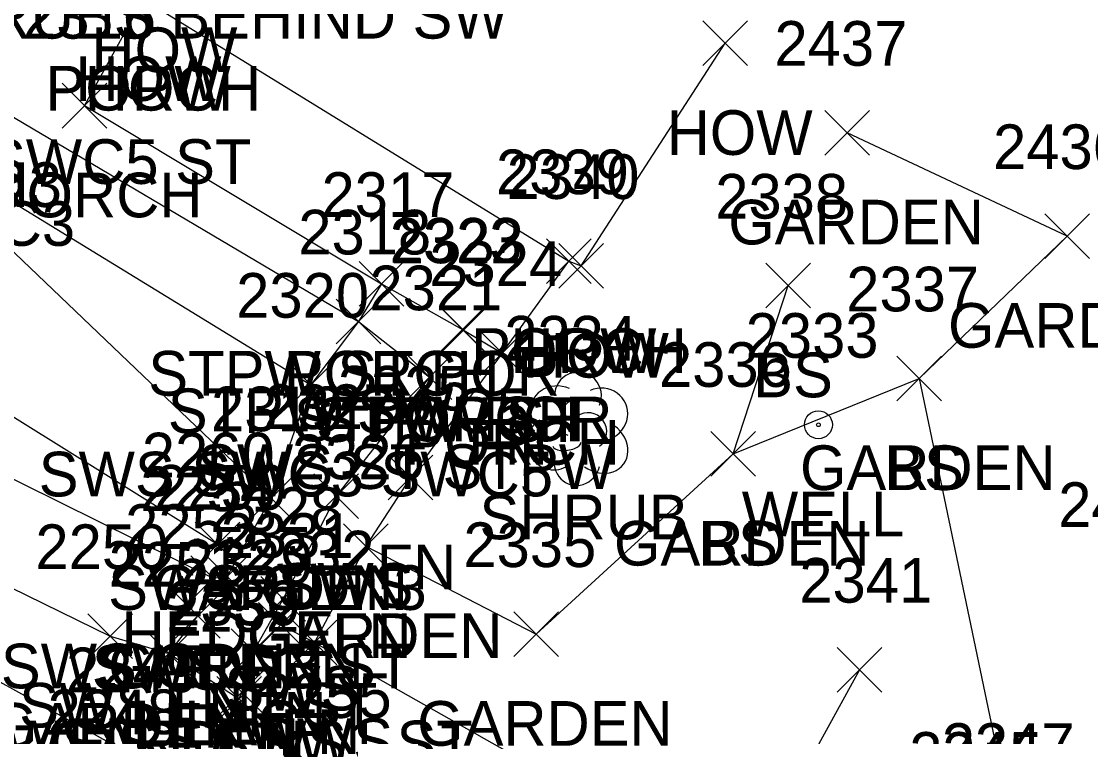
# Model space of a CAD drawing. Extents: x 1499292 to 1501024, y 534584 to 538043.
# Drawn here: x 1499393.02 to 1499440.89, y 537976.07 to 538008.09 of the extents above; entities that cross this region are included whole.
import ezdxf

# ---------------------------------------------------------------- set-up
doc = ezdxf.new("R2010")
doc.units = 0
for name, color, linetype in [('L_A', 7, 'Continuous'), ('L_C', 7, 'Continuous'), ('L_I', 7, 'Continuous'), ('L_TIC', 7, 'Continuous'), ('LAHR', 7, 'Continuous'), ('LAPB', 7, 'Continuous'), ('LBC', 7, 'Continuous'), ('LBF', 7, 'Continuous'), ('LDEFAULT', 7, 'Continuous'), ('LELB', 7, 'Continuous'), ('LFNC', 7, 'Continuous'), ('LSH', 7, 'Continuous'), ('R_A', 7, 'Continuous'), ('R_C', 7, 'Continuous'), ('R_I', 7, 'Continuous'), ('R_TIC', 7, 'Continuous'), ('RSW', 7, 'Continuous'), ('U_A', 7, 'Continuous'), ('U_I', 7, 'Continuous'), ('UWW', 7, 'Continuous')]:
    doc.layers.add(name, color=color, linetype=linetype)

msp = doc.modelspace()

# ---------------------------------------------------------------- linework, layer by layer
at = {"layer": 'L_TIC'}
for points in [[(1499423.526, 538006.115), (1499425.526, 538008.115)], [(1499425.526, 538006.115), (1499423.526, 538008.115)], [(1499394.843, 538003.32), (1499396.843, 538005.32)], [(1499396.843, 538003.32), (1499394.843, 538005.32)], [(1499428.997, 538002.107), (1499430.997, 538004.107)], [(1499430.997, 538002.107), (1499428.997, 538004.107)], [(1499438.84, 537997.481), (1499440.84, 537999.481)], [(1499440.84, 537997.481), (1499438.84, 537999.481)], [(1499416.535, 537996.356), (1499418.535, 537998.356)], [(1499418.535, 537996.356), (1499416.535, 537998.356)], [(1499416.535, 537996.356), (1499418.535, 537998.356)], [(1499418.535, 537996.356), (1499416.535, 537998.356)], [(1499417.089, 537996.143), (1499419.089, 537998.143)], [(1499419.089, 537996.143), (1499417.089, 537998.143)], [(1499408.149, 537995.339), (1499410.149, 537997.339)], [(1499410.149, 537995.339), (1499408.149, 537997.339)], [(1499408.149, 537995.339), (1499410.149, 537997.339)], [(1499410.149, 537995.339), (1499408.149, 537997.339)], [(1499426.345, 537995.262), (1499428.345, 537997.262)], [(1499428.345, 537995.262), (1499426.345, 537997.262)], [(1499407.109, 537993.658), (1499409.109, 537995.658)], [(1499409.109, 537993.658), (1499407.109, 537995.658)], [(1499411.769, 537993.292), (1499413.769, 537995.292)], [(1499413.769, 537993.292), (1499411.769, 537995.292)], [(1499411.769, 537993.292), (1499413.769, 537995.292)], [(1499413.769, 537993.292), (1499411.769, 537995.292)], [(1499411.818, 537993.265), (1499413.818, 537995.265)], [(1499413.818, 537993.265), (1499411.818, 537995.265)], [(1499413.542, 537992.243), (1499415.542, 537994.243)], [(1499415.542, 537992.243), (1499413.542, 537994.243)], [(1499413.542, 537992.243), (1499415.542, 537994.243)], [(1499415.542, 537992.243), (1499413.542, 537994.243)], [(1499410.293, 537991.159), (1499412.293, 537993.159)], [(1499412.293, 537991.159), (1499410.293, 537993.159)], [(1499432.212, 537991.11), (1499434.212, 537993.11)], [(1499434.212, 537991.11), (1499432.212, 537993.11)], [(1499432.212, 537991.11), (1499434.212, 537993.11)], [(1499434.212, 537991.11), (1499432.212, 537993.11)], [(1499423.882, 537987.729), (1499425.882, 537989.729)], [(1499425.882, 537987.729), (1499423.882, 537989.729)], [(1499423.882, 537987.729), (1499425.882, 537989.729)], [(1499425.882, 537987.729), (1499423.882, 537989.729)], [(1499409.444, 537986.67), (1499411.444, 537988.67)], [(1499411.444, 537986.67), (1499409.444, 537988.67)], [(1499403.208, 537985.742), (1499405.208, 537987.742)], [(1499405.208, 537985.742), (1499403.208, 537987.742)], [(1499400.802, 537983.677), (1499402.802, 537985.677)], [(1499402.802, 537983.677), (1499400.802, 537985.677)], [(1499407.442, 537983.592), (1499409.442, 537985.592)], [(1499409.442, 537983.592), (1499407.442, 537985.592)], [(1499407.442, 537983.592), (1499409.442, 537985.592)], [(1499409.442, 537983.592), (1499407.442, 537985.592)], [(1499400.597, 537982.165), (1499402.597, 537984.165)], [(1499402.597, 537982.165), (1499400.597, 537984.165)], [(1499401.231, 537982.233), (1499403.231, 537984.233)], [(1499403.231, 537982.233), (1499401.231, 537984.233)], [(1499399.924, 537980.478), (1499401.924, 537982.478)], [(1499401.924, 537980.478), (1499399.924, 537982.478)], [(1499403.63, 537980.073), (1499405.63, 537982.073)], [(1499405.63, 537980.073), (1499403.63, 537982.073)], [(1499395.992, 537979.573), (1499397.992, 537981.573)], [(1499397.992, 537979.573), (1499395.992, 537981.573)], [(1499405.14, 537979.287), (1499407.14, 537981.287)], [(1499407.14, 537979.287), (1499405.14, 537981.287)], [(1499405.14, 537979.287), (1499407.14, 537981.287)], [(1499407.14, 537979.287), (1499405.14, 537981.287)], [(1499415.069, 537979.662), (1499417.069, 537981.662)], [(1499417.069, 537979.662), (1499415.069, 537981.662)], [(1499398.613, 537978.785), (1499400.613, 537980.785)], [(1499400.613, 537978.785), (1499398.613, 537980.785)], [(1499402.414, 537978.895), (1499404.414, 537980.895)], [(1499404.414, 537978.895), (1499402.414, 537980.895)], [(1499429.543, 537978.068), (1499431.543, 537980.068)], [(1499431.543, 537978.068), (1499429.543, 537980.068)], [(1499401.888, 537977.055), (1499403.888, 537979.055)], [(1499403.888, 537977.055), (1499401.888, 537979.055)], [(1499401.766, 537976.763), (1499403.766, 537978.763)], [(1499403.766, 537976.763), (1499401.766, 537978.763)]]:
    msp.add_lwpolyline(points, dxfattribs=at)
at = {"layer": 'LAHR'}
msp.add_lwpolyline([(1499401.802, 537984.677), (1499380.829, 537997.746), (1499371.736, 538001.851), (1499353.026, 538009.497), (1499334.448, 538017.089)], dxfattribs=at)
at = {"layer": 'LAPB'}
for points in [[(1499344.944, 538025.151), (1499343.901, 538021.262), (1499346.481, 538015.016), (1499362.247, 538007.977), (1499372.995, 538003.698), (1499385.306, 538004.783), (1499404.208, 537986.742)], [(1499325.056, 538023.466), (1499322.984, 538022.224), (1499326.041, 538014.699), (1499358.955, 537999.2), (1499396.992, 537980.573), (1499399.613, 537979.785)], [(1499408.442, 537984.592), (1499416.069, 537980.662), (1499424.882, 537988.729), (1499433.212, 537992.11), (1499439.84, 537998.481), (1499429.997, 538003.107)], [(1499402.766, 537977.763), (1499406.906, 537973.904), (1499417.988, 537967.537)]]:
    msp.add_lwpolyline(points, dxfattribs=at)
at = {"layer": 'LBC'}
msp.add_lwpolyline([(1499398.301, 538013.468), (1499398.768, 538010.822), (1499398.055, 538009.531), (1499398.472, 538009.099), (1499417.535, 537997.356), (1499418.089, 537997.143), (1499424.526, 538007.115)], dxfattribs=at)
at = {"layer": 'LBF'}
for points in [[(1499398.472, 538009.099), (1499395.843, 538004.32), (1499409.149, 537996.339), (1499412.769, 537994.292), (1499414.542, 537993.243), (1499417.535, 537997.356)], [(1499409.149, 537996.339), (1499408.109, 537994.658), (1499411.293, 537992.159)], [(1499412.818, 537994.265), (1499412.769, 537994.292)]]:
    msp.add_lwpolyline(points, dxfattribs=at)
at = {"layer": 'LDEFAULT'}
msp.add_lwpolyline([(1499430.543, 537979.068), (1499425.72, 537970.292)], dxfattribs=at)
at = {"layer": 'LELB'}
for points in [[(1499318.383, 538015.127), (1499358.346, 537997.221), (1499398.285, 537975.056), (1499417.456, 537965.302)], [(1499424.882, 537988.729), (1499427.345, 537996.262)], [(1499433.212, 537992.11), (1499437.487, 537971.67)]]:
    msp.add_lwpolyline(points, dxfattribs=at)
at = {"layer": 'LFNC'}
for points in [[(1499325.056, 538023.466), (1499329.165, 538016.232), (1499360.338, 538003.615), (1499401.597, 537983.165)], [(1499414.542, 537993.243), (1499410.444, 537987.67), (1499408.442, 537984.592), (1499406.14, 537980.287)], [(1499403.414, 537979.895), (1499404.63, 537981.073), (1499406.14, 537980.287), (1499425.77, 537969.179)]]:
    msp.add_lwpolyline(points, dxfattribs=at)
at = {"layer": 'LSH'}
msp.add_line((1499417.899, 537989.907), (1499417.899, 537989.907), dxfattribs=at)
msp.add_line((1499417.899, 537989.907), (1499417.899, 537989.907), dxfattribs=at)
msp.add_arc((1499417.945, 537991.341), 1.047, 335.5272, 180.9563, dxfattribs=at)
for centre, major_axis, ratio, start_param, end_param in [((1499417.107, 537990.574), (1.21, -0.512), 0.895232, 1.570796, 4.712389), ((1499418.94, 537990.491), (-1.141, -0.483), 0.949671, 1.570796, 4.712389), ((1499417.69, 537990.365), (-0.208, -0.792), 0.645439, 3.141593, 6.283185), ((1499418.399, 537989.74), (-0.5, 0.667), 0.989748, 3.141593, 6.283185), ((1499416.815, 537989.199), (0.584, -1.042), 0.959034, 3.141593, 6.283185), ((1499418.899, 537989.074), (-1.09, 0.792), 0.841452, 1.570796, 4.712389), ((1499417.44, 537989.157), (-0.625, -0.083), 0.423636, 0, 3.141593), ((1499417.899, 537988.407), (0.265, 1.061), 0.942809, 1.570796, 4.712389)]:
    msp.add_ellipse(centre, major_axis=major_axis, ratio=ratio, start_param=start_param, end_param=end_param, dxfattribs=at)
at = {"layer": 'R_TIC'}
for points in [[(1499407.109, 537993.658), (1499409.109, 537995.658)], [(1499409.109, 537993.658), (1499407.109, 537995.658)], [(1499404.981, 537990.826), (1499406.981, 537992.826)], [(1499406.981, 537990.826), (1499404.981, 537992.826)], [(1499404.981, 537990.826), (1499406.981, 537992.826)], [(1499406.981, 537990.826), (1499404.981, 537992.826)], [(1499404.981, 537990.826), (1499406.981, 537992.826)], [(1499406.981, 537990.826), (1499404.981, 537992.826)], [(1499410.293, 537991.159), (1499412.293, 537993.159)], [(1499412.293, 537991.159), (1499410.293, 537993.159)], [(1499403.208, 537985.742), (1499405.208, 537987.742)], [(1499405.208, 537985.742), (1499403.208, 537987.742)], [(1499406.116, 537985.84), (1499408.116, 537987.84)], [(1499408.116, 537985.84), (1499406.116, 537987.84)], [(1499400.597, 537982.165), (1499402.597, 537984.165)], [(1499402.597, 537982.165), (1499400.597, 537984.165)], [(1499401.231, 537982.233), (1499403.231, 537984.233)], [(1499403.231, 537982.233), (1499401.231, 537984.233)], [(1499403.737, 537981.239), (1499405.737, 537983.239)], [(1499405.737, 537981.239), (1499403.737, 537983.239)], [(1499399.924, 537980.478), (1499401.924, 537982.478)], [(1499401.924, 537980.478), (1499399.924, 537982.478)], [(1499398.613, 537978.785), (1499400.613, 537980.785)], [(1499400.613, 537978.785), (1499398.613, 537980.785)], [(1499398.613, 537978.785), (1499400.613, 537980.785)], [(1499400.613, 537978.785), (1499398.613, 537980.785)], [(1499402.414, 537978.895), (1499404.414, 537980.895)], [(1499404.414, 537978.895), (1499402.414, 537980.895)], [(1499401.888, 537977.055), (1499403.888, 537979.055)], [(1499403.888, 537977.055), (1499401.888, 537979.055)], [(1499401.888, 537977.055), (1499403.888, 537979.055)], [(1499403.888, 537977.055), (1499401.888, 537979.055)], [(1499401.766, 537976.763), (1499403.766, 537978.763)], [(1499403.766, 537976.763), (1499401.766, 537978.763)]]:
    msp.add_lwpolyline(points, dxfattribs=at)
at = {"layer": 'RSW'}
for points in [[(1499389.242, 538005.816), (1499387.656, 538003.043), (1499405.981, 537991.826)], [(1499389.242, 538005.816), (1499408.109, 537994.658), (1499405.981, 537991.826)], [(1499399.613, 537979.785), (1499400.924, 537981.478), (1499401.597, 537983.165), (1499402.231, 537983.233), (1499404.208, 537986.742), (1499405.981, 537991.826)], [(1499411.293, 537992.159), (1499407.116, 537986.84), (1499404.737, 537982.239), (1499403.414, 537979.895), (1499402.888, 537978.055)], [(1499399.613, 537979.785), (1499402.766, 537977.763), (1499402.888, 537978.055)]]:
    msp.add_lwpolyline(points, dxfattribs=at)
at = {"layer": 'UWW'}
for radius in [0.625, 0.0833]:
    msp.add_circle((1499428.707, 537990.032), radius, dxfattribs=at)

# ---------------------------------------------------------------- texts
at = {"layer": 'L_A'}
for s, p in [('HOW', (1499396.154, 538005.822)), ('HOW', (1499395.441, 538004.531)), ('PORCH', (1499394.094, 538004.099)), ('HOW', (1499395.858, 538004.099)), ('HOW', (1499421.912, 538002.115)), ('PORCH', (1499391.465, 537999.32)), ('GARDEN', (1499424.667, 537998.107)), ('GARDEN', (1499434.509, 537993.481)), ('PORCH', (1499413.157, 537992.356)), ('HOW', (1499414.921, 537992.356)), ('HOW', (1499415.475, 537992.143)), ('STPW ST POR', (1499398.7, 537991.339)), ('PORCH', (1499404.771, 537991.339)), ('BS', (1499425.785, 537991.262)), ('STPW SWC5', (1499399.574, 537989.658)), ('STPW POR', (1499405.218, 537989.292)), ('PORCH', (1499408.391, 537989.292)), ('STPW ST', (1499406.211, 537989.265)), ('PORCH', (1499410.164, 537988.243)), ('FN', (1499413.023, 537988.243)), ('SWS ST STPW', (1499400.883, 537987.159)), ('GARDEN', (1499427.881, 537987.11)), ('BS', (1499431.653, 537987.11)), ('SHRUB', (1499413.528, 537984.907)), ('GARDEN', (1499419.552, 537983.729)), ('BS', (1499423.323, 537983.729)), ('FN', (1499408.924, 537982.67)), ('GARDEN', (1499398.878, 537981.742)), ('HEDGE', (1499397.503, 537979.677)), ('GARDEN', (1499403.112, 537979.592)), ('FN', (1499406.923, 537979.592)), ('GARDEN', (1499396.901, 537978.233)), ('FN', (1499400.077, 537978.165)), ('FN', (1499399.404, 537976.478)), ('FN', (1499403.111, 537976.073)), ('GARDEN', (1499391.661, 537975.573)), ('GARDEN', (1499410.738, 537975.662)), ('FN', (1499404.621, 537975.287)), ('FN', (1499404.621, 537975.287)), ('GARDEN', (1499394.283, 537974.785)), ('FN', (1499401.894, 537974.895))]:
    msp.add_text(s, height=2, dxfattribs=at).set_placement(p)
at = {"layer": 'L_C'}
msp.add_text('LILAC', height=2, dxfattribs=at).set_placement((1499398.078, 537975.677))
at = {"layer": 'L_I'}
for s, p in [('2316', (1499393.095, 538007.32)), ('2437', (1499426.737, 538006.107)), ('2436', (1499436.525, 538001.481)), ('2339', (1499414.267, 538000.356)), ('2339', (1499414.267, 538000.356)), ('2340', (1499414.743, 538000.143)), ('2317', (1499406.456, 537999.339)), ('2317', (1499406.456, 537999.339)), ('2338', (1499424.085, 537999.262)), ('2318', (1499405.416, 537997.658)), ('2323', (1499409.509, 537997.292)), ('2323', (1499409.509, 537997.292)), ('2322', (1499409.558, 537997.265)), ('2324', (1499411.282, 537996.243)), ('2324', (1499411.282, 537996.243)), ('2321', (1499408.6, 537995.159)), ('2337', (1499429.952, 537995.11)), ('2337', (1499429.952, 537995.11)), ('2334', (1499414.639, 537992.907)), ('2336', (1499421.567, 537991.729)), ('2336', (1499421.567, 537991.729)), ('2325', (1499407.184, 537990.67)), ('2319', (1499401.508, 537989.742)), ('2260', (1499398.408, 537987.677)), ('2326', (1499405.128, 537987.592)), ('2326', (1499405.128, 537987.592)), ('2254', (1499398.337, 537986.165)), ('2259', (1499398.964, 537986.233)), ('2434', (1499439.443, 537985.457)), ('2253', (1499397.664, 537984.478)), ('2331', (1499401.938, 537984.073)), ('2250', (1499393.645, 537983.573)), ('2335', (1499412.809, 537983.662)), ('2332', (1499402.88, 537983.287)), ('2332', (1499402.88, 537983.287)), ('2251', (1499396.921, 537982.785)), ('2329', (1499400.146, 537982.895)), ('2341', (1499427.85, 537982.068)), ('2252', (1499399.506, 537980.763)), ('2330', (1499399.542, 537981.055)), ('2249', (1499395.017, 537978.056)), ('2255', (1499403.646, 537976.904)), ('2248', (1499394.188, 537976.179)), ('2347', (1499434.227, 537974.67)), ('2345', (1499432.773, 537974.274))]:
    msp.add_text(s, height=2, dxfattribs=at).set_placement(p)
at = {"layer": 'R_A'}
for s, p in [('SWS5 SWC3 ST SWC5 ST', (1499370.478, 538000.816)), ('SWS5 SWC3 ST SWC5 ST', (1499370.478, 538000.816)), ('SWS5 SWC3 ST SWC5 ST', (1499370.478, 538000.816)), ('SWS3 TS3 GDN3', (1499373.432, 537999.783)), ('SWS3 SWC3', (1499379.373, 537998.043)), ('SWS3 SWC3', (1499379.373, 537998.043)), ('STPW SWC5', (1499399.574, 537989.658)), ('SWS ST STPW', (1499400.883, 537987.159)), ('SWS SWC3 SWC5', (1499393.792, 537986.826)), ('SWS SWC3 SWC5', (1499393.792, 537986.826)), ('SWS SWC3 SWC5', (1499393.792, 537986.826)), ('SWS GDN3', (1499396.901, 537981.742)), ('SWS', (1499404.486, 537981.84)), ('SWS GDN3 ST', (1499392.098, 537978.233)), ('SWS FN', (1499396.171, 537978.165)), ('SWS', (1499402.108, 537977.239)), ('SWS FN1 ST', (1499392.916, 537976.478)), ('GDN SWS ST SWS1 ST', (1499383.81, 537974.785)), ('GDN SWS ST SWS1 ST', (1499383.81, 537974.785)), ('FN ST SWS', (1499395.099, 537974.895))]:
    msp.add_text(s, height=2, dxfattribs=at).set_placement(p)
at = {"layer": 'R_C'}
msp.add_text('FLOWERS AND SHRUBS BEHIND SW', height=2, dxfattribs=at).set_placement((1499367.437, 538007.323))
at = {"layer": 'R_I'}
for s, p in [('2318', (1499405.416, 537997.658)), ('2321', (1499408.6, 537995.159)), ('2320', (1499402.635, 537994.826)), ('2320', (1499402.635, 537994.826)), ('2320', (1499402.635, 537994.826)), ('2327', (1499403.856, 537989.84)), ('2319', (1499401.508, 537989.742)), ('2254', (1499398.337, 537986.165)), ('2259', (1499398.964, 537986.233)), ('2328', (1499401.478, 537985.239)), ('2253', (1499397.664, 537984.478)), ('2251', (1499396.921, 537982.785)), ('2251', (1499396.921, 537982.785)), ('2329', (1499400.146, 537982.895)), ('2252', (1499399.506, 537980.763)), ('2330', (1499399.542, 537981.055)), ('2330', (1499399.542, 537981.055))]:
    msp.add_text(s, height=2, dxfattribs=at).set_placement(p)
at = {"layer": 'U_A'}
msp.add_text('WELL', height=2, dxfattribs=at).set_placement((1499425.274, 537985.032))
at = {"layer": 'U_I'}
msp.add_text('2333', height=2, dxfattribs=at).set_placement((1499425.447, 537993.032))

doc.saveas('drawing.dxf')
